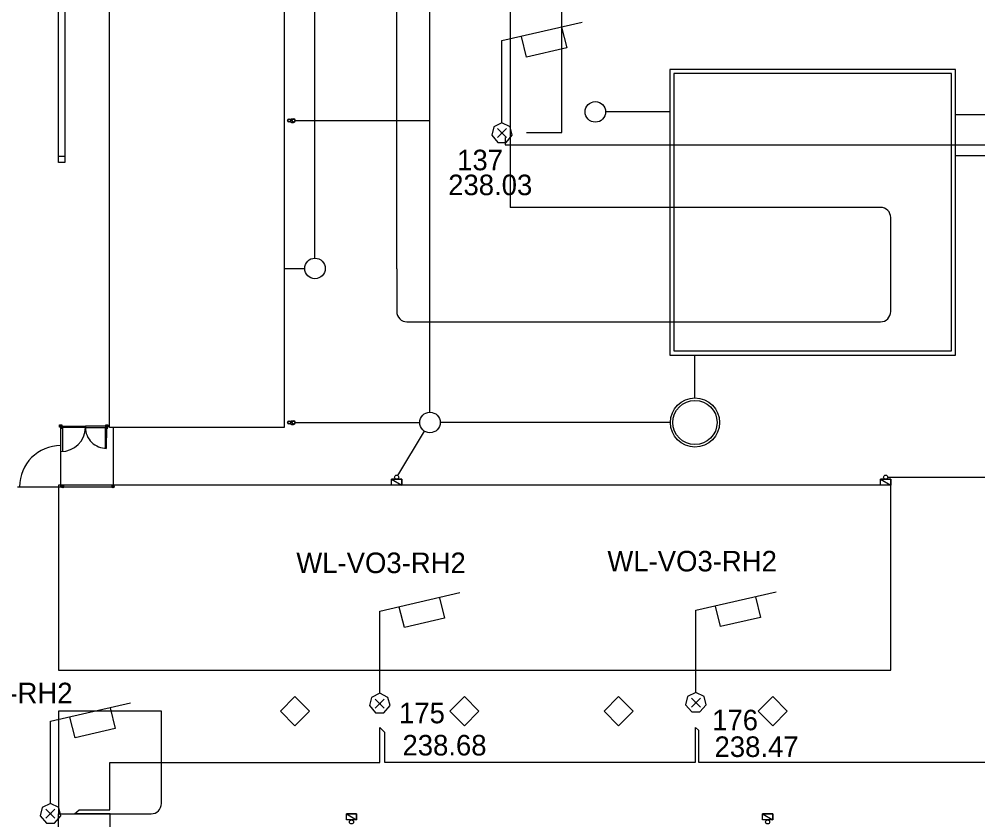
# Model space of a CAD drawing. Extents: x -264222 to -263592, y -1242345 to -1242048.
# Drawn here: x -263971.99 to -263925.35, y -1242271.27 to -1242232.3 of the extents above; entities that cross this region are included whole.
import ezdxf

# ---------------------------------------------------------------- set-up
doc = ezdxf.new("R2010")
doc.units = 0
for name, color, linetype in [('BOD_CISLO', 7, 'Continuous'), ('BOD_SYMBOL', 7, 'Continuous'), ('BOD_VYSKA', 7, 'Continuous'), ('KFA_2D_SITUACIA_DSP', 7, 'Continuous'), ('KFA_SO_62-1_VO_LAMPY_MERANE', 7, 'Continuous'), ('KFA_SO_62-1_VO_POPIS_LAMP_PROJEKT', 7, 'Continuous'), ('KFA_SO_62-1_VO_TRASA_KABLOV_PROJEKT', 7, 'Continuous')]:
    doc.layers.add(name, color=color, linetype=linetype)

msp = doc.modelspace()

# ---------------------------------------------------------------- linework, layer by layer
at = {"layer": 'BOD_SYMBOL'}
for p, q in [((-263948.719, -1242238.065), (-263948.277, -1242237.623)), ((-263948.277, -1242238.065), (-263948.719, -1242237.623)), ((-263954.665, -1242265.834), (-263954.223, -1242265.392)), ((-263954.223, -1242265.834), (-263954.665, -1242265.392)), ((-263939.284, -1242265.789), (-263938.842, -1242265.347)), ((-263938.842, -1242265.789), (-263939.284, -1242265.347)), ((-263970.687, -1242271.198), (-263970.245, -1242270.756)), ((-263970.245, -1242271.198), (-263970.687, -1242270.756))]:
    msp.add_line(p, q, dxfattribs=at)
at = {"layer": 'KFA_2D_SITUACIA_DSP'}
for p, q in [((-263948.093, -1242087.901), (-263948.093, -1242241.458)), ((-263953.617, -1242244.458), (-263953.617, -1242093.307)), ((-263957.597, -1242243.932), (-263957.597, -1242193.383)), ((-263967.593, -1242252.182), (-263967.593, -1242197.782)), ((-263967.593, -1242252.182), (-263967.593, -1242197.782)), ((-263959.097, -1242197.782), (-263959.093, -1242252.182)), ((-263959.093, -1242197.782), (-263959.093, -1242252.182)), ((-263970.07, -1242239.282), (-263970.071, -1242210.684)), ((-263969.77, -1242210.682), (-263969.77, -1242239.282)), ((-263952, -1242251.432), (-263952, -1242223.527)), ((-263926.43, -1242234.749), (-263940.33, -1242234.749)), ((-263940.33, -1242234.749), (-263940.33, -1242248.649)), ((-263926.63, -1242234.949), (-263940.13, -1242234.949)), ((-263940.13, -1242234.949), (-263940.13, -1242248.449)), ((-263926.63, -1242248.449), (-263926.63, -1242234.949)), ((-263926.43, -1242248.649), (-263926.43, -1242234.749)), ((-263940.33, -1242236.811), (-263943.454, -1242236.811)), ((-263919.13, -1242236.949), (-263926.43, -1242236.949)), ((-263958.799, -1242237.162), (-263958.762, -1242237.162)), ((-263958.799, -1242237.302), (-263958.762, -1242237.302)), ((-263958.762, -1242237.162), (-263958.742, -1242237.142)), ((-263958.762, -1242237.302), (-263958.742, -1242237.322)), ((-263958.742, -1242237.142), (-263958.637, -1242237.142)), ((-263958.742, -1242237.322), (-263958.637, -1242237.322)), ((-263958.575, -1242237.232), (-263952, -1242237.232)), ((-263969.77, -1242238.982), (-263970.07, -1242238.982)), ((-263969.77, -1242239.282), (-263970.07, -1242239.282)), ((-263907.219, -1242238.949), (-263926.43, -1242238.949)), ((-263930.081, -1242241.458), (-263948.093, -1242241.458)), ((-263929.582, -1242246.53), (-263929.581, -1242241.959)), ((-263959.097, -1242244.432), (-263958.097, -1242244.432)), ((-263953.617, -1242244.458), (-263953.619, -1242246.529)), ((-263953.119, -1242247.03), (-263930.082, -1242247.03)), ((-263940.33, -1242248.649), (-263926.43, -1242248.649)), ((-263940.13, -1242248.449), (-263926.63, -1242248.449)), ((-263939.13, -1242248.649), (-263939.13, -1242250.737)), ((-263958.799, -1242251.862), (-263958.762, -1242251.862)), ((-263958.762, -1242251.862), (-263958.742, -1242251.842)), ((-263958.742, -1242251.842), (-263958.637, -1242251.842)), ((-263970.018, -1242252.152), (-263970.018, -1242252.052)), ((-263970.018, -1242252.052), (-263969.918, -1242252.052)), ((-263969.918, -1242252.152), (-263970.018, -1242252.152)), ((-263970.005, -1242252.14), (-263970.005, -1242252.065)), ((-263970.005, -1242252.065), (-263969.93, -1242252.065)), ((-263969.93, -1242252.14), (-263970.005, -1242252.14)), ((-263969.93, -1242252.14), (-263969.98, -1242252.14)), ((-263969.98, -1242252.14), (-263969.98, -1242252.24)), ((-263969.98, -1242252.24), (-263969.955, -1242252.24)), ((-263969.968, -1242252.152), (-263969.968, -1242252.202)), ((-263969.968, -1242252.202), (-263969.868, -1242252.202)), ((-263969.955, -1242253.327), (-263969.955, -1242252.19)), ((-263969.955, -1242252.19), (-263969.88, -1242252.19)), ((-263969.93, -1242252.065), (-263969.93, -1242252.14)), ((-263969.918, -1242252.052), (-263969.918, -1242252.152)), ((-263969.918, -1242252.102), (-263968.78, -1242252.102)), ((-263969.918, -1242252.177), (-263969.918, -1242252.102)), ((-263968.78, -1242252.177), (-263969.918, -1242252.177)), ((-263969.88, -1242252.19), (-263969.88, -1242253.327)), ((-263969.868, -1242252.202), (-263969.868, -1242252.177)), ((-263968.78, -1242252.102), (-263968.78, -1242252.177)), ((-263967.768, -1242252.102), (-263968.755, -1242252.102)), ((-263968.755, -1242252.102), (-263968.755, -1242252.177)), ((-263968.755, -1242252.177), (-263967.768, -1242252.177)), ((-263967.818, -1242252.202), (-263967.818, -1242252.177)), ((-263967.718, -1242252.202), (-263967.818, -1242252.202)), ((-263967.805, -1242252.19), (-263967.807, -1242253.177)), ((-263967.73, -1242252.19), (-263967.805, -1242252.19)), ((-263967.768, -1242252.152), (-263967.768, -1242252.052)), ((-263967.768, -1242252.052), (-263967.668, -1242252.052)), ((-263967.768, -1242252.177), (-263967.768, -1242252.102)), ((-263967.668, -1242252.152), (-263967.768, -1242252.152)), ((-263967.755, -1242252.14), (-263967.755, -1242252.065)), ((-263967.755, -1242252.065), (-263967.68, -1242252.065)), ((-263967.755, -1242252.14), (-263967.705, -1242252.14)), ((-263967.68, -1242252.14), (-263967.755, -1242252.14)), ((-263967.732, -1242253.177), (-263967.73, -1242252.19)), ((-263967.705, -1242252.24), (-263967.73, -1242252.24)), ((-263967.718, -1242252.152), (-263967.718, -1242252.202)), ((-263967.705, -1242252.14), (-263967.705, -1242252.24)), ((-263967.68, -1242252.065), (-263967.68, -1242252.14)), ((-263967.668, -1242252.052), (-263967.668, -1242252.152)), ((-263959.093, -1242252.182), (-263967.593, -1242252.182)), ((-263959.093, -1242252.182), (-263967.593, -1242252.182)), ((-263967.418, -1242252.182), (-263967.418, -1242255.057)), ((-263958.799, -1242252.002), (-263958.762, -1242252.002)), ((-263958.762, -1242252.002), (-263958.742, -1242252.022)), ((-263958.742, -1242252.022), (-263958.637, -1242252.022)), ((-263958.575, -1242251.932), (-263952.5, -1242251.932)), ((-263953.57, -1242254.506), (-263952.26, -1242252.359)), ((-263940.302, -1242251.932), (-263951.5, -1242251.932)), ((-263969.968, -1242255.057), (-263969.968, -1242253.057)), ((-263953.87, -1242254.692), (-263953.37, -1242254.692)), ((-263953.87, -1242254.982), (-263953.87, -1242254.692)), ((-263953.87, -1242254.692), (-263953.37, -1242254.982)), ((-263953.87, -1242254.692), (-263953.37, -1242254.982)), ((-263953.37, -1242254.692), (-263953.87, -1242254.692)), ((-263953.37, -1242254.692), (-263953.37, -1242254.982)), ((-263953.37, -1242254.982), (-263953.37, -1242254.692)), ((-263930.08, -1242254.692), (-263929.58, -1242254.692)), ((-263930.08, -1242254.982), (-263930.08, -1242254.692)), ((-263930.08, -1242254.692), (-263929.58, -1242254.982)), ((-263930.08, -1242254.692), (-263929.58, -1242254.982)), ((-263929.58, -1242254.692), (-263930.08, -1242254.692)), ((-263929.73, -1242254.592), (-263920.595, -1242254.592)), ((-263929.58, -1242254.692), (-263929.58, -1242254.982)), ((-263929.58, -1242254.982), (-263929.58, -1242254.692)), ((-263972.068, -1242255.057), (-263967.418, -1242255.057)), ((-263969.928, -1242255.057), (-263969.808, -1242255.057)), ((-263969.868, -1242255.117), (-263969.868, -1242254.997)), ((-263967.478, -1242255.057), (-263967.358, -1242255.057)), ((-263967.418, -1242255.117), (-263967.418, -1242254.997)), ((-263953.37, -1242254.982), (-263953.87, -1242254.982)), ((-263929.58, -1242254.982), (-263930.08, -1242254.982)), ((-263965.068, -1242265.982), (-263970.068, -1242265.982)), ((-263965.068, -1242270.482), (-263965.068, -1242265.982)), ((-263970.065, -1242280.238), (-263970.068, -1242270.982)), ((-263956.068, -1242270.982), (-263955.568, -1242270.982)), ((-263956.068, -1242271.272), (-263956.068, -1242270.982)), ((-263956.068, -1242270.982), (-263955.568, -1242271.272)), ((-263956.068, -1242270.982), (-263955.568, -1242271.272)), ((-263955.568, -1242270.982), (-263956.068, -1242270.982)), ((-263955.568, -1242270.982), (-263955.568, -1242271.272)), ((-263955.568, -1242271.272), (-263955.568, -1242270.982)), ((-263935.824, -1242270.983), (-263935.324, -1242270.983)), ((-263935.824, -1242271.273), (-263935.824, -1242270.983)), ((-263935.824, -1242270.983), (-263935.324, -1242271.273)), ((-263935.824, -1242270.983), (-263935.324, -1242271.273)), ((-263935.324, -1242270.983), (-263935.824, -1242270.983)), ((-263935.324, -1242270.983), (-263935.324, -1242271.273)), ((-263935.324, -1242271.273), (-263935.324, -1242270.983)), ((-263955.568, -1242271.272), (-263956.068, -1242271.272)), ((-263935.324, -1242271.273), (-263935.824, -1242271.273))]:
    msp.add_line(p, q, dxfattribs=at)
for points in [[(-263967.597, -1242197.782), (-263959.097, -1242197.782), (-263959.097, -1242252.182), (-263967.597, -1242252.182)], [(-263958.568, -1242265.275), (-263957.861, -1242265.982), (-263958.568, -1242266.689), (-263959.275, -1242265.982)], [(-263950.324, -1242265.275), (-263949.617, -1242265.982), (-263950.324, -1242266.689), (-263951.031, -1242265.982)], [(-263942.824, -1242265.275), (-263942.117, -1242265.982), (-263942.824, -1242266.689), (-263943.531, -1242265.982)], [(-263935.324, -1242265.275), (-263934.617, -1242265.982), (-263935.324, -1242266.689), (-263936.031, -1242265.982)]]:
    msp.add_lwpolyline(points, close=True, dxfattribs=at)
for points in [[(-263929.58, -1242254.982), (-263970.077, -1242254.982), (-263970.077, -1242263.982), (-263929.58, -1242263.982), (-263929.58, -1242254.982)], [(-263970.068, -1242265.982), (-263970.068, -1242270.982), (-263965.568, -1242270.982)]]:
    msp.add_lwpolyline(points, dxfattribs=at)
for centre, radius in [((-263943.954, -1242236.811), 0.5), ((-263958.847, -1242237.232), 0.085), ((-263958.847, -1242237.232), 0.0625), ((-263958.637, -1242237.232), 0.0625), ((-263957.597, -1242244.432), 0.5), ((-263939.107, -1242251.932), 1.195), ((-263939.107, -1242251.932), 1.075), ((-263952, -1242251.932), 0.5), ((-263958.847, -1242251.932), 0.085), ((-263958.847, -1242251.932), 0.0625), ((-263958.637, -1242251.932), 0.0625), ((-263953.62, -1242254.592), 0.1), ((-263929.83, -1242254.592), 0.1), ((-263969.868, -1242255.057), 0.06), ((-263967.418, -1242255.057), 0.06), ((-263955.818, -1242271.373), 0.1), ((-263935.574, -1242271.373), 0.1)]:
    msp.add_circle(centre, radius, dxfattribs=at)
for centre, radius, start, end in [((-263958.637, -1242237.232), 0.09, 270, 90), ((-263930.081, -1242241.958), 0.5, 359.9785, 89.9999), ((-263953.119, -1242246.53), 0.5, 179.9525, 270), ((-263930.082, -1242246.53), 0.5, 270, 359.9785), ((-263958.637, -1242251.932), 0.09, 270, 90), ((-263969.943, -1242252.165), 1.175, 269.3905, 359.3905), ((-263967.743, -1242252.165), 1.025, 180.6095, 270.6095), ((-263969.968, -1242255.057), 2, 90, 180), ((-263965.568, -1242270.482), 0.5, 270, 0)]:
    msp.add_arc(centre, radius, start, end, dxfattribs=at)
for centre in [(-263969.943, -1242252.165), (-263969.943, -1242252.165), (-263967.743, -1242252.165)]:
    msp.add_ellipse(centre, major_axis=(0, 0.0125), ratio=0.999995, dxfattribs=at)
at = {"layer": 'KFA_SO_62-1_VO_LAMPY_MERANE'}
for p, q in [((-263948.548, -1242237.844), (-263948.448, -1242237.844)), ((-263948.498, -1242237.844), (-263948.498, -1242237.844)), ((-263954.494, -1242265.613), (-263954.394, -1242265.613)), ((-263954.444, -1242265.613), (-263954.444, -1242265.613)), ((-263939.113, -1242265.568), (-263939.013, -1242265.568)), ((-263939.063, -1242265.568), (-263939.063, -1242265.568)), ((-263970.516, -1242270.977), (-263970.416, -1242270.977)), ((-263970.466, -1242270.977), (-263970.466, -1242270.977))]:
    msp.add_line(p, q, dxfattribs=at)
for points in [[(-263948.498, -1242237.344), (-263948.898, -1242237.544), (-263948.998, -1242237.944), (-263948.698, -1242238.294), (-263948.298, -1242238.294), (-263947.998, -1242237.944), (-263948.098, -1242237.544), (-263948.498, -1242237.344), (-263948.498, -1242233.344), (-263944.598, -1242232.444)], [(-263945.598, -1242232.694), (-263945.348, -1242233.694), (-263947.298, -1242234.144), (-263947.548, -1242233.144)], [(-263954.444, -1242265.113), (-263954.844, -1242265.313), (-263954.944, -1242265.713), (-263954.644, -1242266.063), (-263954.244, -1242266.063), (-263953.944, -1242265.713), (-263954.044, -1242265.313), (-263954.444, -1242265.113), (-263954.444, -1242261.113), (-263950.544, -1242260.213)], [(-263939.063, -1242265.068), (-263939.463, -1242265.268), (-263939.563, -1242265.668), (-263939.263, -1242266.018), (-263938.863, -1242266.018), (-263938.563, -1242265.668), (-263938.663, -1242265.268), (-263939.063, -1242265.068), (-263939.063, -1242261.068), (-263935.163, -1242260.168)], [(-263951.544, -1242260.463), (-263951.294, -1242261.463), (-263953.244, -1242261.913), (-263953.494, -1242260.913)], [(-263936.163, -1242260.418), (-263935.913, -1242261.418), (-263937.863, -1242261.868), (-263938.113, -1242260.868)], [(-263970.466, -1242270.477), (-263970.866, -1242270.677), (-263970.966, -1242271.077), (-263970.666, -1242271.427), (-263970.266, -1242271.427), (-263969.966, -1242271.077), (-263970.066, -1242270.677), (-263970.466, -1242270.477), (-263970.466, -1242266.477), (-263966.566, -1242265.577)], [(-263967.566, -1242265.827), (-263967.316, -1242266.827), (-263969.266, -1242267.277), (-263969.516, -1242266.277)]]:
    msp.add_lwpolyline(points, dxfattribs=at)
at = {"layer": 'KFA_SO_62-1_VO_TRASA_KABLOV_PROJEKT'}
for p, q in [((-263945.593, -1242237.814), (-263945.593, -1242217.457)), ((-263947.307, -1242237.814), (-263945.593, -1242237.814)), ((-263948.343, -1242238.057), (-263948.343, -1242238.414)), ((-263948.343, -1242238.414), (-263915.838, -1242238.414)), ((-263954.446, -1242268.482), (-263954.446, -1242266.771)), ((-263954.446, -1242266.771), (-263954.22, -1242267)), ((-263939.08, -1242268.47), (-263939.08, -1242266.772)), ((-263939.08, -1242266.772), (-263938.934, -1242266.901)), ((-263954.22, -1242267), (-263954.22, -1242268.47)), ((-263938.934, -1242266.901), (-263938.934, -1242268.464)), ((-263967.57, -1242270.791), (-263967.57, -1242268.482)), ((-263967.57, -1242268.482), (-263954.446, -1242268.482)), ((-263954.22, -1242268.47), (-263939.08, -1242268.47)), ((-263938.934, -1242268.464), (-263918.745, -1242268.464)), ((-263969.292, -1242270.982), (-263969.07, -1242270.791)), ((-263967.568, -1242270.982), (-263969.292, -1242270.982)), ((-263969.07, -1242270.791), (-263967.57, -1242270.791)), ((-263967.568, -1242285.979), (-263967.568, -1242270.982))]:
    msp.add_line(p, q, dxfattribs=at)

# ---------------------------------------------------------------- texts
at = {"layer": 'BOD_CISLO'}
for s, p in [('137', (-263950.678, -1242239.653)), ('175', (-263953.505, -1242266.573)), ('176', (-263938.271, -1242266.913))]:
    msp.add_text(s, height=1, dxfattribs=at).set_placement(p)
at = {"layer": 'BOD_VYSKA'}
for s, p in [('238.03', (-263951.114, -1242240.865)), ('238.68', (-263953.338, -1242268.139)), ('238.47', (-263938.155, -1242268.212))]:
    msp.add_text(s, height=1, dxfattribs=at).set_placement(p)
at = {"layer": 'KFA_SO_62-1_VO_POPIS_LAMP_PROJEKT'}
for p in [(-263958.505, -1242259.262), (-263943.369, -1242259.18), (-263977.638, -1242265.599)]:
    msp.add_text('WL-VO3-RH2', height=1, dxfattribs=at).set_placement(p)

doc.saveas('drawing.dxf')
